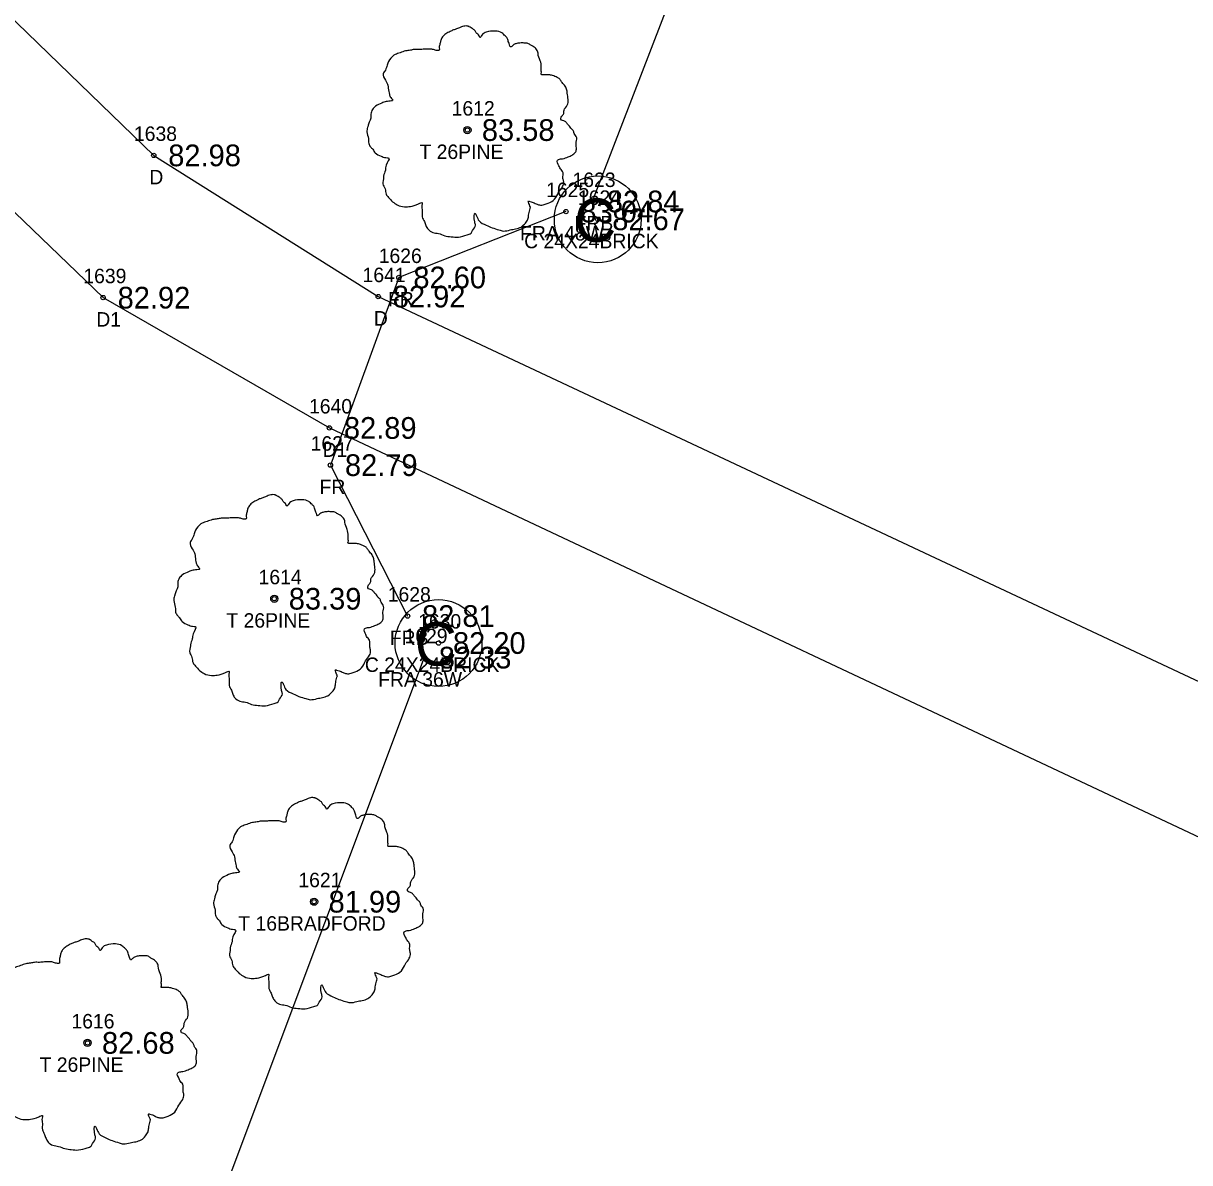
# Model space of a CAD drawing. Extents: x 2139392 to 2143384, y 505395 to 510520.
# Drawn here: x 2140989.6 to 2141070.2, y 509465.1 to 509543.9 of the extents above; entities that cross this region are included whole.
import ezdxf

# ---------------------------------------------------------------- set-up
doc = ezdxf.new("R2010")
doc.units = 0
for name, color, linetype in [('RD_EX_BldgApp', 7, 'Continuous'), ('RD_EX_BldgApp_txCode', 7, 'Continuous'), ('RD_EX_Driveway', 7, 'Continuous'), ('RD_EX_Driveway_txCode', 7, 'Continuous'), ('RD_EX_Fence_Other', 7, 'Continuous'), ('RD_EX_Fence_Other_txCode', 7, 'Continuous'), ('RD_EX_TX_BldgApp_ELEV', 7, 'Continuous'), ('RD_EX_TX_Driveway_ELEV', 7, 'Continuous'), ('RD_EX_TX_Fence_Other_ELEV', 7, 'Continuous'), ('RD_EX_TX_VEG_ELEV', 7, 'Continuous'), ('RD_EX_VEG', 7, 'Continuous'), ('RD_EX_VEG_txCode', 7, 'Continuous'), ('RD_SMD_Locator', 7, 'Continuous')]:
    doc.layers.add(name, color=color, linetype=linetype)

msp = doc.modelspace()

# ---------------------------------------------------------------- linework, layer by layer
at = {"layer": 'RD_EX_BldgApp'}
for centre in [(2141029.295, 509530.308), (2141018.292, 509501.022)]:
    msp.add_circle(centre, 3, dxfattribs=at)
at = {"layer": 'RD_EX_Driveway'}
for points in [[(2140954.315, 509598.009), (2140970.973, 509570.037), (2140984.425, 509549.983), (2140986.949, 509546.035), (2140998.62, 509534.729), (2141014.131, 509524.968), (2141080.244, 509493.941)], [(2140947.592, 509589.318), (2140962.022, 509567.844), (2140979.259, 509540.16), (2140995.124, 509524.894), (2141010.756, 509515.888), (2141076.407, 509484.97)]]:
    msp.add_lwpolyline(points, dxfattribs=at)
at = {"layer": 'RD_EX_Fence_Other'}
for p, q in [((2141045.572, 509574.915), (2141028.917, 509531.544)), ((2141017.31, 509500.011), (2141000.089, 509454.168))]:
    msp.add_line(p, q, dxfattribs=at)
msp.add_lwpolyline([(2141027.092, 509530.846), (2141015.554, 509526.289), (2141010.828, 509513.317), (2141016.154, 509502.886)], dxfattribs=at)
at = {"layer": 'RD_EX_VEG'}
for centre, radius in [((2141020.286, 509536.479), 0.25), ((2141020.274, 509536.46), 0.0001), ((2141006.947, 509504.083), 0.25), ((2141006.934, 509504.064), 0.0001), ((2141009.696, 509483.141), 0.25), ((2141009.683, 509483.122), 0.0001), ((2140994.043, 509473.381), 0.25), ((2140994.03, 509473.362), 0.0001)]:
    msp.add_circle(centre, radius, dxfattribs=at)
for points in [[(2141020.418, 509543.646), (2141020.118, 509543.671), (2141019.793, 509543.571), (2141019.543, 509543.471), (2141019.319, 509543.396), (2141019.094, 509543.296), (2141018.794, 509543.121), (2141018.569, 509542.921), (2141018.444, 509542.671), (2141018.394, 509542.446), (2141018.344, 509542.172), (2141018.344, 509541.997), (2141018.219, 509541.972), (2141018.069, 509541.997), (2141017.819, 509542.072), (2141017.569, 509542.072), (2141017.319, 509542.072), (2141016.97, 509542.047), (2141016.62, 509542.047), (2141016.345, 509541.997), (2141016.02, 509541.947), (2141015.645, 509541.822), (2141015.295, 509541.697), (2141014.995, 509541.447), (2141014.746, 509540.972), (2141014.621, 509540.622), (2141014.471, 509540.372), (2141014.621, 509539.923), (2141014.796, 509539.573), (2141014.82, 509539.373), (2141014.895, 509538.948), (2141014.995, 509538.723), (2141015.12, 509538.523), (2141015.045, 509538.498), (2141014.671, 509538.448), (2141014.371, 509538.348), (2141013.946, 509538.123), (2141013.721, 509537.898), (2141013.621, 509537.574), (2141013.596, 509537.224), (2141013.496, 509537.024), (2141013.421, 509536.749), (2141013.396, 509536.674), (2141013.346, 509536.349), (2141013.446, 509535.899), (2141013.471, 509535.549), (2141013.596, 509535.325), (2141013.746, 509535.15), (2141013.921, 509534.9), (2141014.321, 509534.675), (2141014.646, 509534.575), (2141014.845, 509534.55), (2141014.671, 509534.05), (2141014.621, 509533.7), (2141014.496, 509533.3), (2141014.496, 509533.226), (2141014.446, 509532.751), (2141014.596, 509532.426), (2141014.671, 509532.051), (2141014.845, 509531.826), (2141015.12, 509531.526), (2141015.445, 509531.301), (2141015.945, 509531.176), (2141016.345, 509531.201), (2141016.92, 509531.376), (2141017.169, 509531.451), (2141017.144, 509531.276), (2141017.169, 509530.901), (2141017.169, 509530.477), (2141017.319, 509530.152), (2141017.419, 509529.877), (2141017.569, 509529.627), (2141017.894, 509529.402), (2141018.294, 509529.327), (2141018.719, 509529.177), (2141019.169, 509529.102), (2141019.668, 509529.077), (2141020.268, 509529.227), (2141020.543, 509529.352), (2141020.643, 509529.527), (2141020.843, 509529.902), (2141020.793, 509530.127), (2141020.818, 509530.727), (2141020.918, 509530.552), (2141021.093, 509530.202), (2141021.593, 509529.902), (2141021.992, 509529.727), (2141022.467, 509529.577), (2141022.767, 509529.502), (2141023.242, 509529.577), (2141023.617, 509529.652), (2141023.991, 509529.777), (2141024.291, 509530.052), (2141024.466, 509530.327), (2141024.516, 509530.602), (2141024.591, 509530.976), (2141024.641, 509531.151)], [(2141024.641, 509531.151), (2141024.566, 509531.326), (2141024.516, 509531.576), (2141024.591, 509531.551), (2141024.766, 509531.501), (2141025.041, 509531.376), (2141025.266, 509531.301), (2141025.591, 509531.326), (2141025.866, 509531.426), (2141026.315, 509531.701), (2141026.59, 509532.176), (2141026.865, 509532.576), (2141026.94, 509532.901), (2141026.89, 509533.126), (2141026.865, 509533.625), (2141026.665, 509533.875), (2141026.615, 509534), (2141026.515, 509534.4), (2141026.59, 509534.45), (2141026.865, 509534.5), (2141027.24, 509534.625), (2141027.515, 509534.75), (2141027.74, 509534.925), (2141027.815, 509535.15), (2141027.79, 509535.549), (2141027.84, 509535.949), (2141027.765, 509536.099), (2141027.665, 509536.249), (2141027.59, 509536.449), (2141027.44, 509536.599), (2141027.34, 509536.749), (2141027.24, 509536.849), (2141027.115, 509536.999), (2141026.94, 509537.124), (2141026.79, 509537.174), (2141026.74, 509537.324), (2141026.89, 509537.524), (2141026.94, 509537.624), (2141026.965, 509537.848), (2141027.19, 509538.198), (2141027.24, 509538.598), (2141027.19, 509539.023), (2141027.14, 509539.298), (2141026.99, 509539.573), (2141026.79, 509539.823), (2141026.665, 509539.998), (2141026.49, 509540.122), (2141026.166, 509540.247), (2141025.916, 509540.297), (2141025.566, 509540.297), (2141025.366, 509540.347), (2141025.391, 509540.397), (2141025.391, 509540.547), (2141025.391, 509540.822), (2141025.316, 509541.272), (2141025.166, 509541.772), (2141025.166, 509541.797), (2141025.066, 509542.047), (2141024.841, 509542.247), (2141024.666, 509542.346), (2141024.466, 509542.471), (2141024.216, 509542.496), (2141023.917, 509542.496), (2141023.642, 509542.446), (2141023.442, 509542.346), (2141023.267, 509542.222), (2141023.192, 509542.371), (2141023.092, 509542.671), (2141023.042, 509542.821), (2141022.892, 509542.996), (2141022.667, 509543.196), (2141022.217, 509543.321), (2141021.593, 509543.246), (2141021.293, 509543.046), (2141021.143, 509542.871), (2141021.093, 509542.996), (2141020.893, 509543.196), (2141020.793, 509543.371), (2141020.618, 509543.496), (2141020.468, 509543.596), (2141020.368, 509543.646)], [(2141007.079, 509511.25), (2141006.779, 509511.275), (2141006.454, 509511.175), (2141006.204, 509511.075), (2141005.979, 509511), (2141005.754, 509510.9), (2141005.454, 509510.725), (2141005.23, 509510.525), (2141005.105, 509510.275), (2141005.055, 509510.05), (2141005.005, 509509.775), (2141005.005, 509509.6), (2141004.88, 509509.575), (2141004.73, 509509.6), (2141004.48, 509509.675), (2141004.23, 509509.675), (2141003.98, 509509.675), (2141003.63, 509509.65), (2141003.28, 509509.65), (2141003.006, 509509.6), (2141002.681, 509509.551), (2141002.306, 509509.426), (2141001.956, 509509.301), (2141001.656, 509509.051), (2141001.406, 509508.576), (2141001.281, 509508.226), (2141001.131, 509507.976), (2141001.281, 509507.526), (2141001.456, 509507.177), (2141001.481, 509506.977), (2141001.556, 509506.552), (2141001.656, 509506.327), (2141001.781, 509506.127), (2141001.706, 509506.102), (2141001.331, 509506.052), (2141001.031, 509505.952), (2141000.607, 509505.727), (2141000.382, 509505.502), (2141000.282, 509505.177), (2141000.257, 509504.828), (2141000.157, 509504.628), (2141000.082, 509504.353), (2141000.057, 509504.278), (2141000.007, 509503.953), (2141000.107, 509503.503), (2141000.132, 509503.153), (2141000.257, 509502.928), (2141000.407, 509502.754), (2141000.582, 509502.504), (2141000.981, 509502.279), (2141001.306, 509502.179), (2141001.506, 509502.154), (2141001.331, 509501.654), (2141001.281, 509501.304), (2141001.156, 509500.904), (2141001.156, 509500.829), (2141001.106, 509500.355), (2141001.256, 509500.03), (2141001.331, 509499.655), (2141001.506, 509499.43), (2141001.781, 509499.13), (2141002.106, 509498.905), (2141002.606, 509498.78), (2141003.006, 509498.805), (2141003.58, 509498.98), (2141003.83, 509499.055), (2141003.805, 509498.88), (2141003.83, 509498.505), (2141003.83, 509498.081), (2141003.98, 509497.756), (2141004.08, 509497.481), (2141004.23, 509497.231), (2141004.555, 509497.006), (2141004.955, 509496.931), (2141005.379, 509496.781), (2141005.829, 509496.706), (2141006.329, 509496.681), (2141006.929, 509496.831), (2141007.204, 509496.956), (2141007.304, 509497.131), (2141007.504, 509497.506), (2141007.454, 509497.731), (2141007.479, 509498.33), (2141007.578, 509498.155), (2141007.753, 509497.806), (2141008.253, 509497.506), (2141008.653, 509497.331), (2141009.128, 509497.181), (2141009.428, 509497.106), (2141009.902, 509497.181), (2141010.277, 509497.256), (2141010.652, 509497.381), (2141010.952, 509497.656), (2141011.127, 509497.931), (2141011.177, 509498.205), (2141011.252, 509498.58), (2141011.302, 509498.755)], [(2141011.302, 509498.755), (2141011.227, 509498.93), (2141011.177, 509499.18), (2141011.252, 509499.155), (2141011.427, 509499.105), (2141011.702, 509498.98), (2141011.927, 509498.905), (2141012.251, 509498.93), (2141012.526, 509499.03), (2141012.976, 509499.305), (2141013.251, 509499.78), (2141013.526, 509500.18), (2141013.601, 509500.504), (2141013.551, 509500.729), (2141013.526, 509501.229), (2141013.326, 509501.479), (2141013.276, 509501.604), (2141013.176, 509502.004), (2141013.251, 509502.054), (2141013.526, 509502.104), (2141013.901, 509502.229), (2141014.176, 509502.354), (2141014.401, 509502.529), (2141014.475, 509502.754), (2141014.451, 509503.153), (2141014.5, 509503.553), (2141014.426, 509503.703), (2141014.326, 509503.853), (2141014.251, 509504.053), (2141014.101, 509504.203), (2141014.001, 509504.353), (2141013.901, 509504.453), (2141013.776, 509504.603), (2141013.601, 509504.728), (2141013.451, 509504.778), (2141013.401, 509504.928), (2141013.551, 509505.127), (2141013.601, 509505.227), (2141013.626, 509505.452), (2141013.851, 509505.802), (2141013.901, 509506.202), (2141013.851, 509506.627), (2141013.801, 509506.902), (2141013.651, 509507.177), (2141013.451, 509507.426), (2141013.326, 509507.601), (2141013.151, 509507.726), (2141012.826, 509507.851), (2141012.576, 509507.901), (2141012.226, 509507.901), (2141012.027, 509507.951), (2141012.052, 509508.001), (2141012.052, 509508.151), (2141012.052, 509508.426), (2141011.977, 509508.876), (2141011.827, 509509.376), (2141011.827, 509509.401), (2141011.727, 509509.65), (2141011.502, 509509.85), (2141011.327, 509509.95), (2141011.127, 509510.075), (2141010.877, 509510.1), (2141010.577, 509510.1), (2141010.302, 509510.05), (2141010.102, 509509.95), (2141009.927, 509509.825), (2141009.852, 509509.975), (2141009.753, 509510.275), (2141009.703, 509510.425), (2141009.553, 509510.6), (2141009.328, 509510.8), (2141008.878, 509510.925), (2141008.253, 509510.85), (2141007.953, 509510.65), (2141007.803, 509510.475), (2141007.753, 509510.6), (2141007.553, 509510.8), (2141007.454, 509510.975), (2141007.279, 509511.1), (2141007.129, 509511.2), (2141007.029, 509511.25)], [(2141009.828, 509490.308), (2141009.528, 509490.333), (2141009.203, 509490.233), (2141008.953, 509490.133), (2141008.728, 509490.058), (2141008.504, 509489.958), (2141008.204, 509489.783), (2141007.979, 509489.583), (2141007.854, 509489.333), (2141007.804, 509489.108), (2141007.754, 509488.834), (2141007.754, 509488.659), (2141007.629, 509488.634), (2141007.479, 509488.659), (2141007.229, 509488.734), (2141006.979, 509488.734), (2141006.729, 509488.734), (2141006.379, 509488.709), (2141006.03, 509488.709), (2141005.755, 509488.659), (2141005.43, 509488.609), (2141005.055, 509488.484), (2141004.705, 509488.359), (2141004.405, 509488.109), (2141004.155, 509487.634), (2141004.03, 509487.284), (2141003.881, 509487.034), (2141004.03, 509486.585), (2141004.205, 509486.235), (2141004.23, 509486.035), (2141004.305, 509485.61), (2141004.405, 509485.385), (2141004.53, 509485.185), (2141004.455, 509485.16), (2141004.08, 509485.11), (2141003.781, 509485.01), (2141003.356, 509484.785), (2141003.131, 509484.56), (2141003.031, 509484.236), (2141003.006, 509483.886), (2141002.906, 509483.686), (2141002.831, 509483.411), (2141002.806, 509483.336), (2141002.756, 509483.011), (2141002.856, 509482.561), (2141002.881, 509482.211), (2141003.006, 509481.987), (2141003.156, 509481.812), (2141003.331, 509481.562), (2141003.731, 509481.337), (2141004.055, 509481.237), (2141004.255, 509481.212), (2141004.08, 509480.712), (2141004.03, 509480.362), (2141003.906, 509479.962), (2141003.906, 509479.888), (2141003.856, 509479.413), (2141004.005, 509479.088), (2141004.08, 509478.713), (2141004.255, 509478.488), (2141004.53, 509478.188), (2141004.855, 509477.963), (2141005.355, 509477.838), (2141005.755, 509477.863), (2141006.33, 509478.038), (2141006.579, 509478.113), (2141006.554, 509477.938), (2141006.579, 509477.563), (2141006.579, 509477.139), (2141006.729, 509476.814), (2141006.829, 509476.539), (2141006.979, 509476.289), (2141007.304, 509476.064), (2141007.704, 509475.989), (2141008.129, 509475.839), (2141008.579, 509475.764), (2141009.078, 509475.739), (2141009.678, 509475.889), (2141009.953, 509476.014), (2141010.053, 509476.189), (2141010.253, 509476.564), (2141010.203, 509476.789), (2141010.228, 509477.389), (2141010.328, 509477.214), (2141010.503, 509476.864), (2141011.002, 509476.564), (2141011.402, 509476.389), (2141011.877, 509476.239), (2141012.177, 509476.164), (2141012.652, 509476.239), (2141013.027, 509476.314), (2141013.401, 509476.439), (2141013.701, 509476.714), (2141013.876, 509476.989), (2141013.926, 509477.264), (2141014.001, 509477.638), (2141014.051, 509477.813)], [(2141014.051, 509477.813), (2141013.976, 509477.988), (2141013.926, 509478.238), (2141014.001, 509478.213), (2141014.176, 509478.163), (2141014.451, 509478.038), (2141014.676, 509477.963), (2141015.001, 509477.988), (2141015.276, 509478.088), (2141015.725, 509478.363), (2141016, 509478.838), (2141016.275, 509479.238), (2141016.35, 509479.563), (2141016.3, 509479.788), (2141016.275, 509480.287), (2141016.075, 509480.537), (2141016.025, 509480.662), (2141015.925, 509481.062), (2141016, 509481.112), (2141016.275, 509481.162), (2141016.65, 509481.287), (2141016.925, 509481.412), (2141017.15, 509481.587), (2141017.225, 509481.812), (2141017.2, 509482.211), (2141017.25, 509482.611), (2141017.175, 509482.761), (2141017.075, 509482.911), (2141017, 509483.111), (2141016.85, 509483.261), (2141016.75, 509483.411), (2141016.65, 509483.511), (2141016.525, 509483.661), (2141016.35, 509483.786), (2141016.2, 509483.836), (2141016.15, 509483.986), (2141016.3, 509484.186), (2141016.35, 509484.286), (2141016.375, 509484.51), (2141016.6, 509484.86), (2141016.65, 509485.26), (2141016.6, 509485.685), (2141016.55, 509485.96), (2141016.4, 509486.235), (2141016.2, 509486.485), (2141016.075, 509486.66), (2141015.9, 509486.784), (2141015.575, 509486.909), (2141015.326, 509486.959), (2141014.976, 509486.959), (2141014.776, 509487.009), (2141014.801, 509487.059), (2141014.801, 509487.209), (2141014.801, 509487.484), (2141014.726, 509487.934), (2141014.576, 509488.434), (2141014.576, 509488.459), (2141014.476, 509488.709), (2141014.251, 509488.909), (2141014.076, 509489.008), (2141013.876, 509489.133), (2141013.626, 509489.158), (2141013.326, 509489.158), (2141013.052, 509489.108), (2141012.852, 509489.008), (2141012.677, 509488.884), (2141012.602, 509489.033), (2141012.502, 509489.333), (2141012.452, 509489.483), (2141012.302, 509489.658), (2141012.077, 509489.858), (2141011.627, 509489.983), (2141011.002, 509489.908), (2141010.703, 509489.708), (2141010.553, 509489.533), (2141010.503, 509489.658), (2141010.303, 509489.858), (2141010.203, 509490.033), (2141010.028, 509490.158), (2141009.878, 509490.258), (2141009.778, 509490.308)], [(2140994.174, 509480.548), (2140993.875, 509480.573), (2140993.55, 509480.473), (2140993.3, 509480.373), (2140993.075, 509480.298), (2140992.85, 509480.198), (2140992.55, 509480.023), (2140992.325, 509479.823), (2140992.2, 509479.574), (2140992.15, 509479.349), (2140992.1, 509479.074), (2140992.1, 509478.899), (2140991.975, 509478.874), (2140991.825, 509478.899), (2140991.576, 509478.974), (2140991.326, 509478.974), (2140991.076, 509478.974), (2140990.726, 509478.949), (2140990.376, 509478.949), (2140990.101, 509478.899), (2140989.776, 509478.849), (2140989.402, 509478.724), (2140989.052, 509478.599), (2140988.752, 509478.349), (2140988.502, 509477.874), (2140988.377, 509477.524), (2140988.227, 509477.275), (2140988.377, 509476.825), (2140988.552, 509476.475), (2140988.577, 509476.275), (2140988.652, 509475.85), (2140988.752, 509475.625), (2140988.877, 509475.425), (2140988.802, 509475.4), (2140988.427, 509475.35), (2140988.127, 509475.25), (2140987.702, 509475.026), (2140987.477, 509474.801), (2140987.377, 509474.476), (2140987.352, 509474.126), (2140987.253, 509473.926), (2140987.178, 509473.651), (2140987.153, 509473.576), (2140987.103, 509473.251), (2140987.203, 509472.801), (2140987.228, 509472.452), (2140987.352, 509472.227), (2140987.502, 509472.052), (2140987.677, 509471.802), (2140988.077, 509471.577), (2140988.402, 509471.477), (2140988.602, 509471.452), (2140988.427, 509470.952), (2140988.377, 509470.602), (2140988.252, 509470.203), (2140988.252, 509470.128), (2140988.202, 509469.653), (2140988.352, 509469.328), (2140988.427, 509468.953), (2140988.602, 509468.728), (2140988.877, 509468.428), (2140989.202, 509468.204), (2140989.701, 509468.079), (2140990.101, 509468.104), (2140990.676, 509468.278), (2140990.926, 509468.353), (2140990.901, 509468.179), (2140990.926, 509467.804), (2140990.926, 509467.379), (2140991.076, 509467.054), (2140991.176, 509466.779), (2140991.326, 509466.529), (2140991.651, 509466.304), (2140992.05, 509466.229), (2140992.475, 509466.079), (2140992.925, 509466.004), (2140993.425, 509465.979), (2140994.025, 509466.129), (2140994.299, 509466.254), (2140994.399, 509466.429), (2140994.599, 509466.804), (2140994.549, 509467.029), (2140994.574, 509467.629), (2140994.674, 509467.454), (2140994.849, 509467.104), (2140995.349, 509466.804), (2140995.749, 509466.629), (2140996.224, 509466.479), (2140996.523, 509466.404), (2140996.998, 509466.479), (2140997.373, 509466.554), (2140997.748, 509466.679), (2140998.048, 509466.954), (2140998.223, 509467.229), (2140998.273, 509467.504), (2140998.348, 509467.879), (2140998.398, 509468.054)], [(2140998.398, 509468.054), (2140998.323, 509468.229), (2140998.273, 509468.478), (2140998.348, 509468.453), (2140998.523, 509468.403), (2140998.797, 509468.278), (2140999.022, 509468.204), (2140999.347, 509468.229), (2140999.622, 509468.328), (2141000.072, 509468.603), (2141000.347, 509469.078), (2141000.622, 509469.478), (2141000.697, 509469.803), (2141000.647, 509470.028), (2141000.622, 509470.527), (2141000.422, 509470.777), (2141000.372, 509470.902), (2141000.272, 509471.302), (2141000.347, 509471.352), (2141000.622, 509471.402), (2141000.996, 509471.527), (2141001.271, 509471.652), (2141001.496, 509471.827), (2141001.571, 509472.052), (2141001.546, 509472.452), (2141001.596, 509472.851), (2141001.521, 509473.001), (2141001.421, 509473.151), (2141001.346, 509473.351), (2141001.196, 509473.501), (2141001.096, 509473.651), (2141000.996, 509473.751), (2141000.872, 509473.901), (2141000.697, 509474.026), (2141000.547, 509474.076), (2141000.497, 509474.226), (2141000.647, 509474.426), (2141000.697, 509474.526), (2141000.722, 509474.751), (2141000.947, 509475.1), (2141000.996, 509475.5), (2141000.947, 509475.925), (2141000.897, 509476.2), (2141000.747, 509476.475), (2141000.547, 509476.725), (2141000.422, 509476.9), (2141000.247, 509477.025), (2140999.922, 509477.15), (2140999.672, 509477.2), (2140999.322, 509477.2), (2140999.122, 509477.25), (2140999.147, 509477.3), (2140999.147, 509477.449), (2140999.147, 509477.724), (2140999.072, 509478.174), (2140998.922, 509478.674), (2140998.922, 509478.699), (2140998.822, 509478.949), (2140998.598, 509479.149), (2140998.423, 509479.249), (2140998.223, 509479.374), (2140997.973, 509479.399), (2140997.673, 509479.399), (2140997.398, 509479.349), (2140997.198, 509479.249), (2140997.023, 509479.124), (2140996.948, 509479.274), (2140996.848, 509479.574), (2140996.798, 509479.723), (2140996.648, 509479.898), (2140996.424, 509480.098), (2140995.974, 509480.223), (2140995.349, 509480.148), (2140995.049, 509479.948), (2140994.899, 509479.773), (2140994.849, 509479.898), (2140994.649, 509480.098), (2140994.549, 509480.273), (2140994.374, 509480.398), (2140994.224, 509480.498), (2140994.124, 509480.548)]]:
    msp.add_spline(points, degree=3, dxfattribs=at)
at = {"layer": 'RD_SMD_Locator'}
for centre in [(2141020.286, 509536.479), (2140998.62, 509534.729), (2141028.917, 509531.544), (2141027.092, 509530.846), (2141029.295, 509530.308), (2141015.554, 509526.289), (2140995.124, 509524.894), (2141014.131, 509524.968), (2141010.756, 509515.888), (2141010.828, 509513.317), (2141006.947, 509504.083), (2141016.154, 509502.886), (2141018.292, 509501.022), (2141017.31, 509500.011), (2141009.696, 509483.141), (2140994.043, 509473.381)]:
    msp.add_circle(centre, 0.15, dxfattribs=at)

# ---------------------------------------------------------------- texts
at = {"layer": 'RD_EX_BldgApp'}
for p in [(2141027.664, 509528.746), (2141016.661, 509499.461)]:
    msp.add_text('C', height=3, dxfattribs=at).set_placement(p)
at = {"layer": 'RD_EX_BldgApp_txCode'}
for s, p in [('1624', (2141027.925, 509531.308)), ('C 24X24BRICK', (2141024.208, 509528.308)), ('1630', (2141016.883, 509502.022)), ('C 24X24BRICK', (2141013.205, 509499.022))]:
    msp.add_text(s, height=1, dxfattribs=at).set_placement(p)
at = {"layer": 'RD_EX_Driveway_txCode'}
for s, p in [('1638', (2140997.25, 509535.729)), ('D', (2140998.313, 509532.729)), ('1639', (2140993.754, 509525.894)), ('1641', (2141013.045, 509525.968)), ('D1', (2140994.651, 509522.894)), ('D', (2141013.824, 509522.968)), ('1640', (2141009.346, 509516.888)), ('D1', (2141010.283, 509513.888))]:
    msp.add_text(s, height=1, dxfattribs=at).set_placement(p)
at = {"layer": 'RD_EX_Fence_Other_txCode'}
for s, p in [('1623', (2141027.547, 509532.544)), ('1625', (2141025.722, 509531.846)), ('FRA 48W', (2141023.927, 509528.846)), ('FRB', (2141027.688, 509529.544)), ('1626', (2141014.16, 509527.289)), ('FR', (2141014.798, 509524.289)), ('1627', (2141009.458, 509514.317)), ('FR', (2141010.072, 509511.317)), ('1628', (2141014.784, 509503.886)), ('FRB', (2141014.925, 509500.886)), ('1629', (2141015.94, 509501.011)), ('FRA 36W', (2141014.121, 509498.011))]:
    msp.add_text(s, height=1, dxfattribs=at).set_placement(p)
at = {"layer": 'RD_EX_TX_BldgApp_ELEV'}
for s, p in [('82.67', (2141030.295, 509529.558)), ('82.20', (2141019.292, 509500.272))]:
    msp.add_text(s, height=1.5, dxfattribs=at).set_placement(p)
at = {"layer": 'RD_EX_TX_Driveway_ELEV'}
for s, p in [('82.98', (2140999.62, 509533.979)), ('82.92', (2140996.124, 509524.144)), ('82.92', (2141015.131, 509524.218)), ('82.89', (2141011.756, 509515.138))]:
    msp.add_text(s, height=1.5, dxfattribs=at).set_placement(p)
at = {"layer": 'RD_EX_TX_Fence_Other_ELEV'}
for s, p in [('82.84', (2141029.917, 509530.794)), ('83.04', (2141028.092, 509530.096)), ('82.60', (2141016.554, 509525.539)), ('82.79', (2141011.828, 509512.567)), ('82.81', (2141017.154, 509502.136)), ('82.33', (2141018.31, 509499.261))]:
    msp.add_text(s, height=1.5, dxfattribs=at).set_placement(p)
at = {"layer": 'RD_EX_TX_VEG_ELEV'}
for s, p in [('83.58', (2141021.286, 509535.729)), ('83.39', (2141007.947, 509503.333)), ('81.99', (2141010.696, 509482.391)), ('82.68', (2140995.043, 509472.631))]:
    msp.add_text(s, height=1.5, dxfattribs=at).set_placement(p)
at = {"layer": 'RD_EX_VEG_txCode'}
for s, p in [('1612', (2141019.199, 509537.479)), ('T 26PINE', (2141016.975, 509534.479)), ('1614', (2141005.86, 509505.083)), ('T 26PINE', (2141003.636, 509502.083)), ('1621', (2141008.609, 509484.141)), ('T 16BRADFORD', (2141004.46, 509481.141)), ('1616', (2140992.932, 509474.381)), ('T 26PINE', (2140990.731, 509471.381))]:
    msp.add_text(s, height=1, dxfattribs=at).set_placement(p)

doc.saveas('drawing.dxf')
